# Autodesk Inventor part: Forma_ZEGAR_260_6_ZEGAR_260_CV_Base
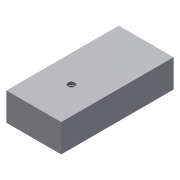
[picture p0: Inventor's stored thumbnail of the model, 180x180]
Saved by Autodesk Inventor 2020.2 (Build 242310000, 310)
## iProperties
Created: 2015-01
Part Number: Forma_ZEGAR_260_6_ZEGAR_260_CV_Base
Material: Ogólny
Document SubType Name: Modeling
Designer: F.Stasiak
Density: 1 g/cm^3
Appearance: Domyślna
Catalog Web Link: www.expertbooks.pl
Manager: www.cadconsulting.pl
Company: Fabian Stasiak CAD Consulting
Author: F.Stasiak
Subject: Zbiór ćwiczeń. Autodesk Inventor 2020. Kurs Professional
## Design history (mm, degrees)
node "Forma_ZEGAR_260_4_ZEGAR_260_MP"
sketch "Szkic1"
  geometry: 1 further point
hole "Otwór1" sketch "Szkic1" at (39, -106.407) diameter "d0" = 7; stored, may be unused: countersink angle "d4" = 90 deg, drill point angle "d6" = 118 deg; dims "d1" = 6, "d2" = 10, "d3" = 4, "d5" = 15
feature "Rzeźbienie2"
feature "Bryła4::Forma_ZEGAR_260_4_ZEGAR_260_MP"
tag "Bryła wyprowadzona1"
node "Bryła1"
feature "Forma_ZEGAR_260_4_ZEGAR_260_MP_Bodies"
feature "Powierzchnia2"
body "Srf2"
